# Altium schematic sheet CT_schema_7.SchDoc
size 218 x 258 mm
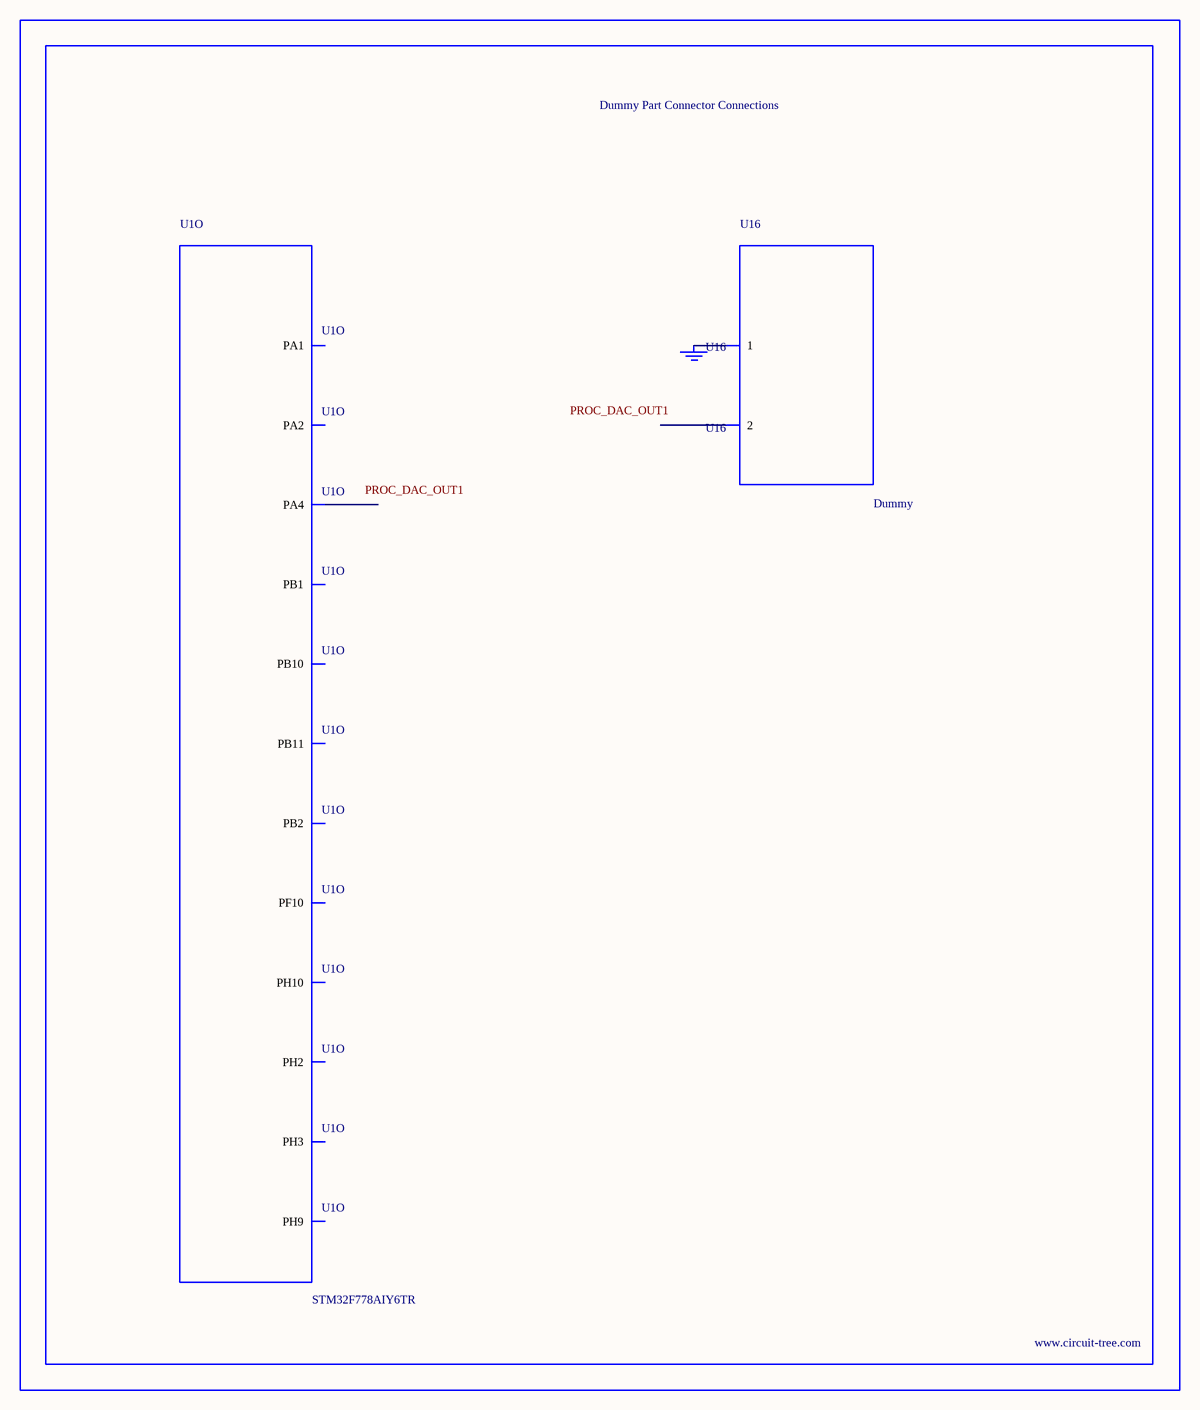
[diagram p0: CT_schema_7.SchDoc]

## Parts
BORDER6  (no value)
GND_INSTANCE_6_0  (no value)
U1  STM32F778AIY6TR  [WLCSP180]  (part O of 15)
U16  Dummy  [DUMMY_PACKAGE_192]

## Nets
NetGND_INSTANCE_6_0_0: GND_INSTANCE_6_0.0(GND) U16.1

Not connected (* = marked no-connect by the designer): U1 J7(PB2) J8(PB1) J10(PA2) J11(PA1) K4(PH9) K5(PB10) K10(PH3) K11(PF10) L4(PH10) L5(PB11) L9(PA4) L10(PH2); U16 2

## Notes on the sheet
- Labels drawn without touching a wire or pin: PROC_DAC_OUT1

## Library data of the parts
BORDER6 = BORDER_PAGE6
GND_INSTANCE_6_0 = GND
